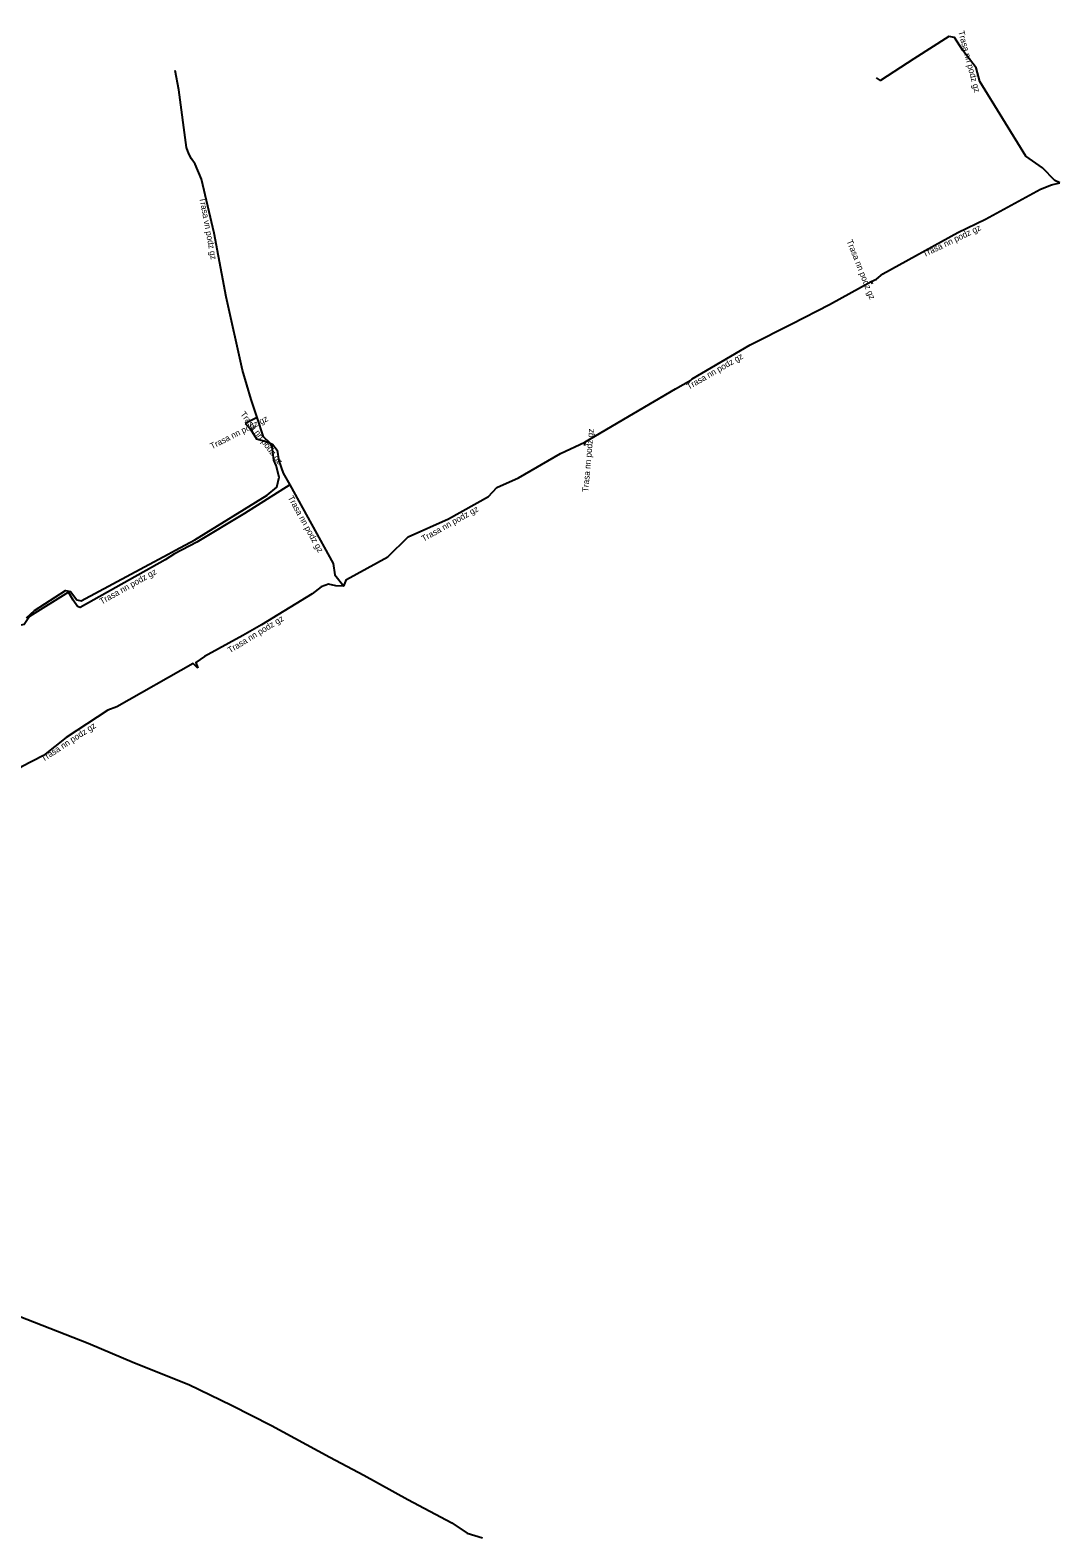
# Model space of a CAD drawing. Extents: x -687924 to -686708, y -1056742 to -1056249.
# Drawn here: x -687598.7 to -687515.1, y -1056668.6 to -1056546.2 of the extents above; entities that cross this region are included whole.
import ezdxf

# ---------------------------------------------------------------- set-up
doc = ezdxf.new("R2010")
doc.units = 0
for name, color, linetype in [('Popiskový text - Ostatní atributy Trasy', 7, 'Continuous'), ('Spojnice NN', 7, 'Continuous'), ('Spojnice VN', 7, 'Continuous')]:
    doc.layers.add(name, color=color, linetype=linetype)

msp = doc.modelspace()

# ---------------------------------------------------------------- linework, layer by layer
at = {"layer": 'Spojnice NN'}
for points in [[(-687515.05, -1056558.56), (-687515.47, -1056558.37), (-687516.46, -1056557.34), (-687517.82, -1056556.41), (-687521.55, -1056550.33), (-687521.85, -1056549.22), (-687522.94, -1056547.81), (-687523.62, -1056546.77), (-687524.08, -1056546.69), (-687526.9, -1056548.5), (-687529.63, -1056550.25), (-687529.94, -1056550.04)], [(-687530.38, -1056566.58), (-687529.95, -1056566.39), (-687529.44, -1056565.96), (-687523.35, -1056562.59), (-687521.09, -1056561.51), (-687516.62, -1056559.08), (-687515.72, -1056558.73), (-687515.05, -1056558.56)], [(-687553.64, -1056579.63), (-687553.22, -1056579.37), (-687549.68, -1056577.3), (-687546.26, -1056575.29), (-687545.03, -1056574.58), (-687544.92, -1056574.47), (-687540.2, -1056571.73), (-687536.83, -1056570.01), (-687533.75, -1056568.45), (-687530.38, -1056566.58)], [(-687530.38, -1056566.58), (-687530.3, -1056566.77)], [(-687580.26, -1056577.62), (-687581.22, -1056578.11)], [(-687581.22, -1056578.11), (-687580.79, -1056578.57), (-687580.3, -1056579.36), (-687579.64, -1056579.55), (-687579, -1056579.78), (-687578.62, -1056580.28), (-687578.49, -1056581.15), (-687578.14, -1056582.13), (-687577.6, -1056583.1)], [(-687573.2, -1056591.33), (-687572.99, -1056590.78), (-687569.65, -1056588.93), (-687567.99, -1056587.31), (-687564.7, -1056585.84), (-687561.47, -1056584.03), (-687560.77, -1056583.3), (-687559.01, -1056582.52), (-687555.61, -1056580.54), (-687553.64, -1056579.63)], [(-687553.64, -1056579.63), (-687553.67, -1056579.89)], [(-687577.6, -1056583.1), (-687581.29, -1056585.41), (-687585.15, -1056587.74), (-687586.96, -1056588.7), (-687587.72, -1056589.18), (-687594.63, -1056593.05), (-687594.85, -1056592.97), (-687595.19, -1056592.46), (-687595.58, -1056591.82), (-687598.75, -1056593.78), (-687599.17, -1056594.44), (-687599.88, -1056594.58), (-687601.07, -1056595.06), (-687601.5, -1056594.72)], [(-687577.6, -1056583.1), (-687574.07, -1056589.47), (-687573.95, -1056590.4), (-687573.2, -1056591.33)], [(-687573.2, -1056591.33), (-687573.86, -1056591.28), (-687574.46, -1056591.17), (-687575.05, -1056591.37), (-687575.79, -1056591.95), (-687579.91, -1056594.47), (-687581.41, -1056595.32), (-687584.52, -1056597.02), (-687585.23, -1056597.51), (-687585.07, -1056597.97)], [(-687585.07, -1056597.97), (-687585.45, -1056597.61), (-687591.64, -1056601.13), (-687592.37, -1056601.39), (-687595.77, -1056603.62), (-687597.6, -1056605.08), (-687599.38, -1056605.98), (-687602.39, -1056607.73), (-687603.93, -1056608.7), (-687603.97, -1056609.01)]]:
    msp.add_lwpolyline(points, dxfattribs=at)
at = {"layer": 'Spojnice VN'}
for points in [[(-687580.26, -1056577.62), (-687580.74, -1056576.17), (-687581.44, -1056573.77), (-687582.78, -1056567.81), (-687583.75, -1056562.65), (-687584.76, -1056558.26), (-687585.3, -1056557.05), (-687585.59, -1056556.62), (-687585.79, -1056556.2), (-687586, -1056555.69), (-687586.6, -1056551.01), (-687586.91, -1056549.45)], [(-687598.98, -1056593.9), (-687598.35, -1056593.3), (-687595.82, -1056591.68), (-687595.42, -1056591.75), (-687594.89, -1056592.43), (-687594.55, -1056592.5), (-687589.39, -1056589.75), (-687587.47, -1056588.72), (-687586.88, -1056588.39), (-687585.32, -1056587.56), (-687579.43, -1056583.94), (-687578.66, -1056583.28), (-687578.45, -1056582.47), (-687578.7, -1056581.53), (-687578.9, -1056581.09), (-687579.02, -1056580), (-687579.19, -1056579.72), (-687579.74, -1056579.19), (-687580.26, -1056577.62)], [(-687599.59, -1056650.62), (-687593.98, -1056652.79), (-687590.22, -1056654.4), (-687585.79, -1056656.15), (-687582.33, -1056657.83), (-687579.08, -1056659.49), (-687574.35, -1056662.07), (-687571.59, -1056663.51), (-687568.01, -1056665.49), (-687564.43, -1056667.38), (-687563.19, -1056668.23), (-687561.96, -1056668.61)]]:
    msp.add_lwpolyline(points, dxfattribs=at)

# ---------------------------------------------------------------- texts
at = {"layer": 'Popiskový text - Ostatní atributy Trasy'}
for s, rotation, p in [('Trasa nn podz gz', 284.9857, (-687523.31, -1056546.28)), ('Trasa vn podz gz', 280.6491, (-687584.95, -1056559.79)), ('Trasa nn podz gz', 25.6443, (-687526.06, -1056564.61)), ('Trasa nn podz gz', 291.6485, (-687532.38, -1056563.29)), ('Trasa nn podz gz', 30.0848, (-687545.19, -1056575.38)), ('Trasa nn podz gz', 26.8796, (-687583.92, -1056580.21)), ('Trasa nn podz gz', 307.2348, (-687581.65, -1056577.36)), ('Trasa nn podz gz', 84.8461, (-687553.36, -1056583.7)), ('Trasa nn podz gz', 299.0149, (-687577.78, -1056584.13)), ('Trasa nn podz gz', 29.2505, (-687566.73, -1056587.72)), ('Trasa nn podz gz', 29.2514, (-687592.88, -1056592.82)), ('Trasa nn podz gz', 31.4521, (-687582.45, -1056596.78)), ('Trasa nn podz gz', 33.2638, (-687597.61, -1056605.6))]:
    msp.add_text(s, height=0.5, rotation=rotation, dxfattribs=at).set_placement(p)

doc.saveas('drawing.dxf')
